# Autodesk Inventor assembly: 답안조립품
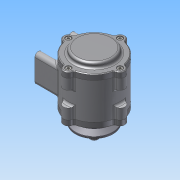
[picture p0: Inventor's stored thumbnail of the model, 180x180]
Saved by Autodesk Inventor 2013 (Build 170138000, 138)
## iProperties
Created: 2015-03
Part Number: 답안조립품
Document SubType Name: Assembly
Designer: ST3
Author: ST3
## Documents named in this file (10)
- C:\Users\ST3\Desktop\450305V1042\답안조립품.iam
- C:\Users\ST3\Desktop\450305V1042\1-본체.ipt
- C:\Users\ST3\Desktop\450305V1042\축.ipt
- C:\Users\ST3\Desktop\450305V1042\V벨트풀리.ipt
- C:\Users\ST3\Desktop\450305V1042\커버.ipt
- C:\Users\ST3\Desktop\450305V1042\베어링 6204.ipt
- C:\Users\ST3\Desktop\450305V1042\오일실.ipt
- C:\Users\ST3\Desktop\450305V1042\커버2.ipt
- C:\Users\ST3\Desktop\450305V1042\키(4 x 4 x 12).ipt
- C:\Users\ST3\Desktop\450305V1042\M 4 x 12.ipt
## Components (14 placed, 6 different names)
1. 1-본체:1
2. 그루브 풀리1:1
3. KS B 2023 6204 - 20 x 47 x 14:1
4. KS B 2023 6204 - 20 x 47 x 14:2
5. KS B 2804 D D - 20 32 8:1
6. KS B 1311 (I) 4 x 4 x 12:1
7. KS B 1003 - 미터 M 4 x 12:1
8. KS B 1003 - 미터 M 4 x 12:2
9. KS B 1003 - 미터 M 4 x 12:3
10. KS B 1003 - 미터 M 4 x 12:4
11. KS B 1003 - 미터 M 4 x 12:5
12. KS B 1003 - 미터 M 4 x 12:6
13. KS B 1003 - 미터 M 4 x 12:7
14. KS B 1003 - 미터 M 4 x 12:8
